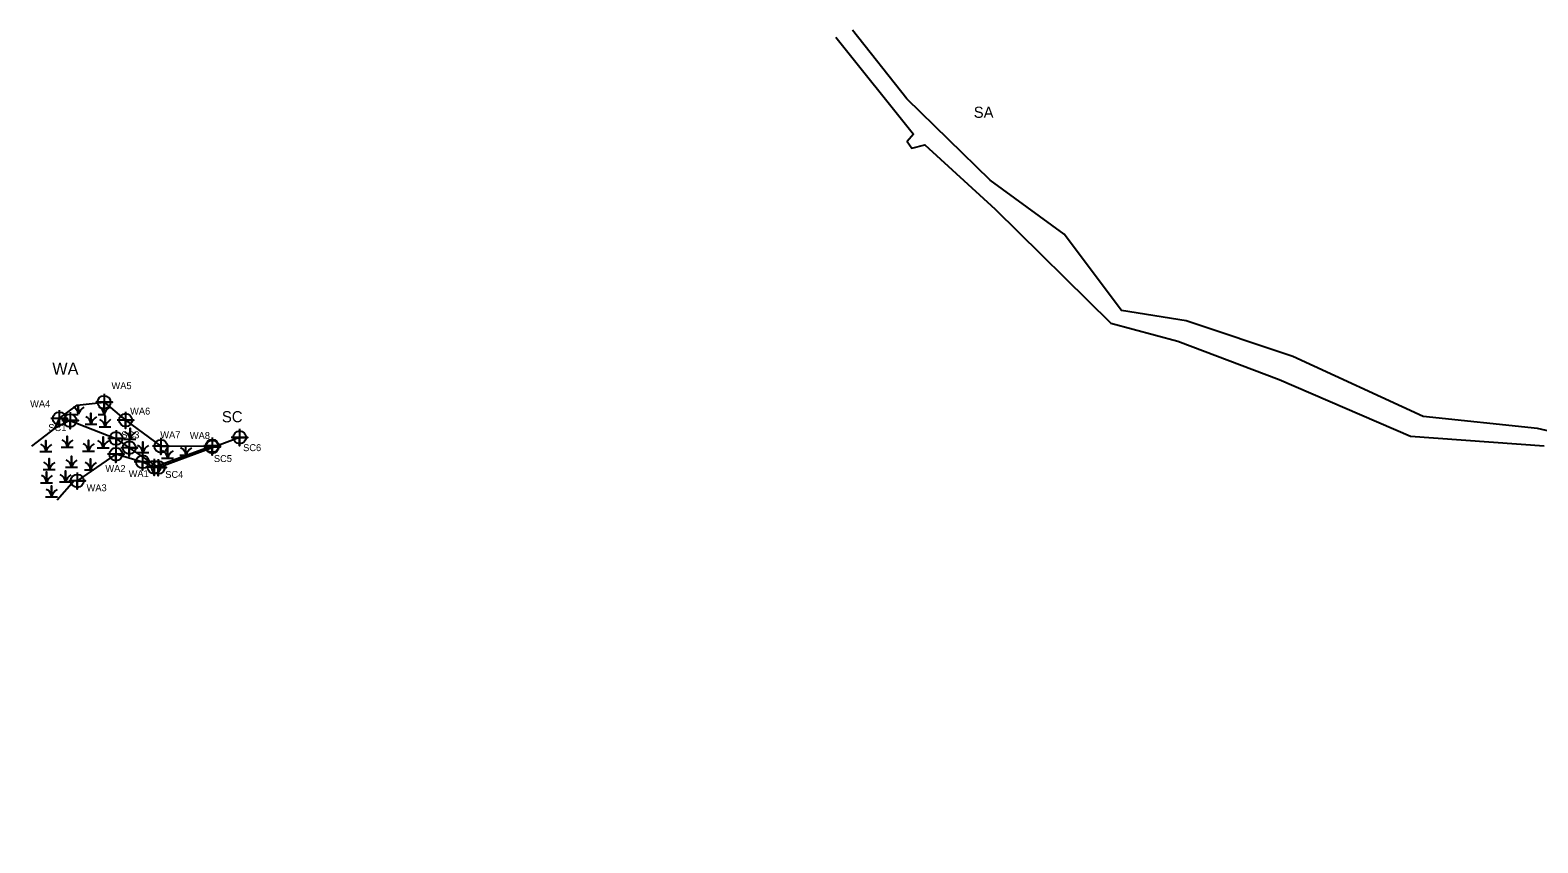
# Model space of a CAD drawing. Extents: x 1581951 to 1583895, y 930673 to 932553.
# Drawn here: x 1581951 to 1582493, y 932260 to 932553 of the extents above; entities that cross this region are included whole.
import ezdxf

# ---------------------------------------------------------------- set-up
doc = ezdxf.new("R2010")
doc.units = 0
for name, color, linetype in [('Exist Environmental Wetland Boundary', 7, 'Continuous'), ('Exist Environmental Wetland Boundary Cogo Comment', 7, 'Continuous'), ('Exist Environmental Wetland Boundary Cogo Point CELL', 7, 'Continuous'), ('Exist Hydro Jurisdictional Stream or Body of Water NEU Mitigable', 7, 'Continuous'), ('Exist Hydro Jurisdictional Stream or Body of Water NEU Mitigable Cogo Comment', 7, 'Continuous'), ('Exist Hydro Jurisdictional Stream or Body of Water NEU Mitigable Cogo Point CELL', 7, 'Continuous')]:
    doc.layers.add(name, color=color, linetype=linetype)

msp = doc.modelspace()

# ---------------------------------------------------------------- linework, layer by layer
at = {"layer": 'Exist Environmental Wetland Boundary'}
for p, q in [((1581967.91, 932414.49), (1581967.91, 932417.88)), ((1581967.91, 932417.88), (1581967.91, 932414.49)), ((1581961.05, 932412.91), (1581959.34, 932409.38)), ((1581965.76, 932414.42), (1581967.88, 932414.42)), ((1581959.34, 932409.38), (1581951.1, 932402.99))]:
    msp.add_line(p, q, dxfattribs=at)
for points in [[(1581961.05, 932412.91), (1581967.54, 932417.77), (1581977.19, 932418.79), (1581984.94, 932412.38), (1581997.64, 932402.92), (1582016.28, 932403.04), (1581995.26, 932395.39), (1581991.04, 932397.2), (1581981.46, 932400.04), (1581967.51, 932390.49)], [(1581975.06, 932414.42), (1581977.21, 932414.42), (1581977.21, 932417.84)], [(1581977.21, 932417.84), (1581977.21, 932414.42), (1581977.72, 932414.42)], [(1581970.32, 932410.93), (1581972.47, 932410.93), (1581972.47, 932414.88), (1581972.47, 932410.93), (1581974.62, 932410.93)], [(1581975.37, 932409.97), (1581977.52, 932409.97), (1581977.52, 932413.91), (1581977.52, 932409.97), (1581979.67, 932409.97)], [(1581961.78, 932402.59), (1581963.93, 932402.59), (1581963.93, 932406.53), (1581963.93, 932402.59), (1581966.08, 932402.59)], [(1581984.36, 932405.48), (1581986.51, 932405.48), (1581986.51, 932409.42), (1581986.51, 932405.48), (1581988.66, 932405.48)], [(1581954.11, 932401.06), (1581956.26, 932401.06), (1581956.26, 932405.01), (1581956.26, 932401.06), (1581958.41, 932401.06)], [(1581969.41, 932401.23), (1581971.56, 932401.23), (1581971.56, 932405.18), (1581971.56, 932401.23), (1581973.71, 932401.23)], [(1581974.66, 932402.37), (1581976.81, 932402.37), (1581976.81, 932406.32), (1581976.81, 932402.37), (1581978.96, 932402.37)], [(1581988.96, 932400.64), (1581991.11, 932400.64), (1581991.11, 932404.59), (1581991.11, 932400.64), (1581993.26, 932400.64)], [(1581997.87, 932398.7), (1582000.02, 932398.7), (1582000.02, 932402.65), (1582000.02, 932398.7), (1582002.17, 932398.7)], [(1582004.49, 932399.76), (1582006.64, 932399.76), (1582006.64, 932402.99)], [(1581955.28, 932394.59), (1581957.43, 932394.59), (1581957.43, 932398.53), (1581957.43, 932394.59), (1581959.58, 932394.59)], [(1581963.28, 932395.44), (1581965.43, 932395.44), (1581965.43, 932399.38), (1581965.43, 932395.44), (1581967.58, 932395.44)], [(1581970.16, 932394.49), (1581972.31, 932394.49), (1581972.31, 932398.43), (1581972.31, 932394.49), (1581973.35, 932394.49)], [(1581954.35, 932389.83), (1581956.5, 932389.83), (1581956.5, 932393.77), (1581956.5, 932389.83), (1581958.65, 932389.83)], [(1581967.51, 932390.49), (1581966.45, 932390.46), (1581960.29, 932383.51)], [(1581961.11, 932390.13), (1581963.26, 932390.13), (1581963.26, 932394.08), (1581963.26, 932390.13), (1581965.42, 932390.13)], [(1581956.13, 932384.8), (1581958.28, 932384.8), (1581958.28, 932388.75), (1581958.28, 932384.8), (1581960.43, 932384.8)]]:
    msp.add_lwpolyline(points, dxfattribs=at)
for centre, radius, start, end in [((1581964.84, 932414.2), 3.07, 5.1768, 67.535), ((1581972.47, 932412.91), 4.81, 122.1274, 159.1605), ((1581969.4, 932410.71), 3.07, 4.1403, 67.535), ((1581977.03, 932409.42), 4.81, 122.1274, 161.6222), ((1581974.14, 932414.2), 3.07, 4.1403, 67.535), ((1581974.46, 932409.74), 3.07, 4.1403, 67.535), ((1581981.77, 932412.91), 4.81, 122.1274, 161.6222), ((1581982.08, 932408.45), 4.81, 122.1274, 161.6222), ((1581983.44, 932405.25), 3.07, 4.1403, 67.535), ((1581991.07, 932403.96), 4.81, 122.1274, 161.6222), ((1581953.19, 932400.84), 3.07, 4.1403, 67.535), ((1581960.82, 932399.55), 4.81, 122.1274, 161.6222), ((1581960.87, 932402.36), 3.07, 4.1403, 67.535), ((1581968.49, 932401.07), 4.81, 122.1274, 161.6222), ((1581968.5, 932401.01), 3.07, 4.1403, 67.535), ((1581976.12, 932399.72), 4.81, 122.1274, 161.6222), ((1581973.75, 932402.15), 3.07, 4.1403, 67.535), ((1581981.38, 932400.86), 4.81, 122.1274, 161.6222), ((1581988.04, 932400.42), 3.07, 4.1403, 67.535), ((1581995.67, 932399.13), 4.81, 122.1274, 161.6222), ((1581996.95, 932398.48), 3.07, 4.1403, 67.535), ((1582004.58, 932397.19), 4.81, 122.1274, 161.6222), ((1582003.57, 932399.54), 3.07, 4.1403, 67.535), ((1582011.2, 932398.25), 4.81, 122.1274, 161.6222), ((1581954.36, 932394.37), 3.07, 4.1403, 67.535), ((1581961.99, 932393.07), 4.81, 122.1274, 161.6222), ((1581962.37, 932395.22), 3.07, 4.1403, 67.535), ((1581969.99, 932393.92), 4.81, 122.1274, 161.6222), ((1581969.25, 932394.27), 3.07, 4.1403, 67.535), ((1581976.87, 932392.97), 4.81, 122.1274, 161.6222), ((1581953.44, 932389.6), 3.07, 4.1403, 67.535), ((1581961.06, 932388.31), 4.81, 122.1274, 161.6222), ((1581960.2, 932389.91), 3.07, 4.1403, 67.535), ((1581967.83, 932388.62), 4.81, 122.1274, 161.6222), ((1581955.21, 932384.58), 3.07, 4.1403, 67.535), ((1581962.84, 932383.29), 4.81, 122.1274, 161.6222)]:
    msp.add_arc(centre, radius, start, end, dxfattribs=at)
at = {"layer": 'Exist Environmental Wetland Boundary Cogo Point CELL'}
for points in [[(1581977.19, 932421.79), (1581977.19, 932415.79), (1581977.19, 932418.79), (1581980.19, 932418.79), (1581974.19, 932418.79)], [(1581961.05, 932415.91), (1581961.05, 932409.91), (1581961.05, 932412.91), (1581964.05, 932412.91), (1581958.05, 932412.91)], [(1581984.94, 932415.38), (1581984.94, 932409.38), (1581984.94, 932412.38), (1581987.94, 932412.38), (1581981.94, 932412.38)], [(1581981.46, 932403.04), (1581981.46, 932397.04), (1581981.46, 932400.04), (1581984.46, 932400.04), (1581978.46, 932400.04)], [(1581997.64, 932405.92), (1581997.64, 932399.92), (1581997.64, 932402.92), (1582000.64, 932402.92), (1581994.64, 932402.92)], [(1582016.09, 932406.04), (1582016.09, 932400.04), (1582016.09, 932403.04), (1582019.09, 932403.04), (1582013.09, 932403.04)], [(1581991.04, 932400.34), (1581991.04, 932394.34), (1581991.04, 932397.34), (1581994.04, 932397.34), (1581988.04, 932397.34)], [(1581995.19, 932398.39), (1581995.19, 932392.39), (1581995.19, 932395.39), (1581998.19, 932395.39), (1581992.19, 932395.39)], [(1581967.51, 932393.49), (1581967.51, 932387.49), (1581967.51, 932390.49), (1581970.51, 932390.49), (1581964.51, 932390.49)]]:
    msp.add_lwpolyline(points, dxfattribs=at)
for centre in [(1581977.19, 932418.79), (1581961.05, 932412.91), (1581984.94, 932412.38), (1581981.46, 932400.04), (1581997.64, 932402.92), (1582016.09, 932403.04), (1581991.04, 932397.34), (1581995.19, 932395.39), (1581967.51, 932390.49)]:
    msp.add_circle(centre, 2.34, dxfattribs=at)
at = {"layer": 'Exist Hydro Jurisdictional Stream or Body of Water NEU Mitigable'}
for p, q in [((1581964.9, 932412.15), (1581959.34, 932409.38)), ((1581959.34, 932409.38), (1581951.1, 932402.99))]:
    msp.add_line(p, q, dxfattribs=at)
for points in [[(1582240.51, 932550.18), (1582268.57, 932515.2), (1582266.18, 932512.62), (1582267.92, 932510.15), (1582272.56, 932511.38), (1582297.93, 932488.3), (1582339.53, 932447.18), (1582363.7, 932440.74), (1582400.13, 932426.95), (1582447.4, 932406.6), (1582495.46, 932403.11)], [(1582806.96, 932054.77), (1582795.58, 932072.13), (1582774.68, 932097.01), (1582746.86, 932109.65), (1582704.89, 932124.68), (1582691.62, 932149.02), (1582676.04, 932170.24), (1582653.67, 932180.31), (1582632.67, 932192.2), (1582612.36, 932210.9), (1582587.44, 932257.63), (1582583.08, 932293.35), (1582558.73, 932325.5), (1582528.88, 932359.41), (1582510.32, 932405.32), (1582493.1, 932409.34), (1582451.98, 932413.59), (1582404.99, 932435.19), (1582366.69, 932448.04), (1582343.42, 932451.84), (1582322.76, 932479.22), (1582296.07, 932498.69), (1582266.13, 932527.89), (1582246.61, 932552.65)], [(1581964.9, 932412.15), (1581981.46, 932405.76), (1581986.24, 932402.43), (1581996.62, 932395.31), (1582016.11, 932402.47), (1582025.98, 932406.18)]]:
    msp.add_lwpolyline(points, dxfattribs=at)
for centre, radius, start, end in [((1581980.58, 932412.99), 3.07, 4.1403, 15.8726), ((1581988.2, 932411.69), 4.81, 156.9688, 161.6222)]:
    msp.add_arc(centre, radius, start, end, dxfattribs=at)
at = {"layer": 'Exist Hydro Jurisdictional Stream or Body of Water NEU Mitigable Cogo Point CELL'}
for points in [[(1581964.92, 932415.15), (1581964.92, 932409.15), (1581964.92, 932412.15), (1581967.92, 932412.15), (1581961.92, 932412.15)], [(1581981.48, 932408.76), (1581981.48, 932402.76), (1581981.48, 932405.76), (1581984.48, 932405.76), (1581978.48, 932405.76)], [(1582025.98, 932409.15), (1582025.98, 932403.15), (1582025.98, 932406.15), (1582028.98, 932406.15), (1582022.98, 932406.15)], [(1581986.24, 932405.43), (1581986.24, 932399.43), (1581986.24, 932402.43), (1581989.24, 932402.43), (1581983.24, 932402.43)], [(1582016.11, 932405.68), (1582016.11, 932399.68), (1582016.11, 932402.68), (1582019.11, 932402.68), (1582013.11, 932402.68)], [(1581996.68, 932398.31), (1581996.68, 932392.31), (1581996.68, 932395.31), (1581999.68, 932395.31), (1581993.68, 932395.31)]]:
    msp.add_lwpolyline(points, dxfattribs=at)
for centre in [(1581964.92, 932412.15), (1581981.48, 932405.76), (1582025.98, 932406.15), (1581986.24, 932402.43), (1582016.11, 932402.68), (1581996.68, 932395.31)]:
    msp.add_circle(centre, 2.34, dxfattribs=at)

# ---------------------------------------------------------------- texts
at = {"layer": 'Exist Environmental Wetland Boundary Cogo Comment'}
for s, height, p in [('WA', 4.375, (1581958.54, 932428.69)), ('WA5', 2.5, (1581979.84, 932423.49)), ('WA4', 2.5, (1581950.56, 932416.97)), ('WA6', 2.5, (1581986.54, 932414.34)), ('WA7', 2.5, (1581997.4, 932405.81)), ('WA8', 2.5, (1582008.04, 932405.54)), ('WA2', 2.5, (1581977.65, 932393.68)), ('WA1', 2.5, (1581986.02, 932391.83)), ('WA3', 2.5, (1581970.88, 932386.75))]:
    msp.add_text(s, height=height, dxfattribs=at).set_placement(p)
at = {"layer": 'Exist Hydro Jurisdictional Stream or Body of Water NEU Mitigable Cogo Comment'}
for s, height, p in [('SA', 4, (1582290.19, 932521.11)), ('SC', 4, (1582019.59, 932411.57)), ('SC1', 2.5, (1581957.1, 932408.4)), ('SC3', 2.5, (1581983.39, 932405.81)), ('SC6', 2.5, (1582027.22, 932401.18)), ('SC5', 2.5, (1582016.7, 932397.26)), ('SC4', 2.5, (1581999.2, 932391.55))]:
    msp.add_text(s, height=height, dxfattribs=at).set_placement(p)

doc.saveas('drawing.dxf')
